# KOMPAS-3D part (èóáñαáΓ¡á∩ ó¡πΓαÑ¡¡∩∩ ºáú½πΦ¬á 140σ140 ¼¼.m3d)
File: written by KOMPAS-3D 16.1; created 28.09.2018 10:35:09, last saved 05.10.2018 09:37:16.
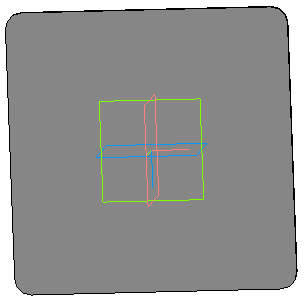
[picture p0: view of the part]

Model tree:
1. Эскиз:1
2. Операция выдавливания:1
     Расстояние 1 = 2
3. Скругление:1  (labels: Квадратная внутренняя заглушка 140х140 мм)
     Радиус = 8

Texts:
  Body Specification ( left align )
  Body Specificaton ( centered )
